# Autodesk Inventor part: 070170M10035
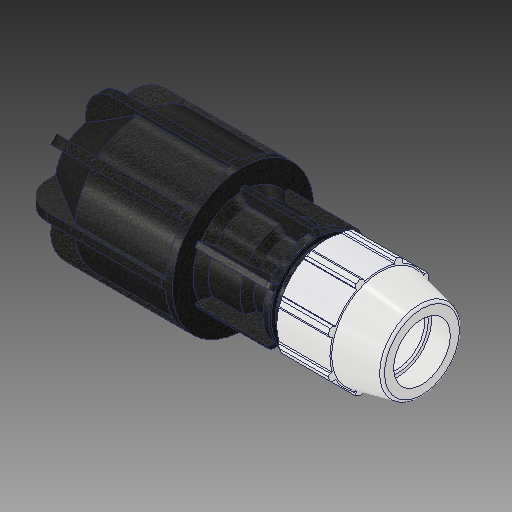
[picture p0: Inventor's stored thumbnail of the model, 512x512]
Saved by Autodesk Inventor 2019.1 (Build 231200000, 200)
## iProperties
Created: 2017-02
Part Number: 070170M10035
Material: PVC-Piping
Description: PLASSON PLASS4 COUPLING 1'' - 1.22
Document SubType Name: Modeling
Designer: KIM
Mass: 92.6774 g
Surface Area: 199.44 cm^2
Volume: 66.1981 cm^3
Density: 1.4 g/cm^3
Appearance: PTFE
Author: KIM
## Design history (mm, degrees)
derived "070170M0.ipt"
feature "Solid1::070170M0.ipt"
tag "TaggingFeature1"
body "Solid1"
other parameters: "d_" = 33.3, "E_" = 62.992, "A_" = 81, "l_" = 70.104, "d_1" = 30.988, "E_1" = 83.058, "l_1" = 89.916, "H_" = 195.072, "d106" = 41.71618, "d2" = 33.3, "d4" = 13.93371, "d5" = 24.5364, "d7" = 62.992, "d8" = 41.71618, "d9" = 11.57143, "d11" = 4.8768, "d12" = 50.3936, "d13" = 120 deg, "d14" = 46.62, "d15" = 12 deg, "d16" = 56.6928, "d18" = 1.665, "d19" = 35 deg, "d20" = 17.5 deg, "d21" = 58.58256, "d23" = 0, "d25" = 360 deg, "d27" = 1.25984, "d42" = 31.5468, "d43" = 1.88976, "d46" = 0.999, "d53" = 0.666, "d67" = 3.1496, "d70" = 29.97, "d71" = 70.104, "d74" = 180 deg, "d75" = 30.988, "d76" = 83.058, "d80" = 29.97, "d84" = 78.9051, "d85" = 135 deg, "d86" = 4.1529, "d89" = 4.1529, "d90" = 135 deg, "d94" = 4.1529, "d97" = 5.03936, "d98" = 0, "d100" = 360 deg, "d102" = 91.3638, "d103" = 16.6116, "d104" = 6.64464, "d105" = 0, "d110" = 89.916, "d112" = 117.0432, "d113" = 30.57144, "d114" = 78.0288, "d115" = 49.8348, "d116" = 117.0432, "d117" = 4.4958, "d118" = 31.496, "d119" = 3.1496, "d120" = 0, "d121" = 3.1496, "d123" = 360 deg
